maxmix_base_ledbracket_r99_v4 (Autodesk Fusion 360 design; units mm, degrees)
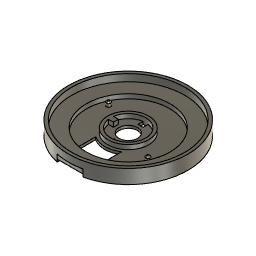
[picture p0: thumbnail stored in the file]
sketch "Sketch1" plane through (0, 0, 0) normal (0, 0, 1) x axis (1, 0, 0)
  circle C1 centre (0, 0) radius 22.95
  circle C2 centre (0, 0) radius 6.75
  circle C3 centre (0, 0) radius 21.75
  circle C4 centre (0, 0) radius 3.6
  circle C5 centre (0, 0) radius 7.9
  point P1 (0, 0)
  point P2 (0, 0)
  point P3 (0, 0)
  point P4 (0, 0)
  coincident P1 P2
  coincident P1 P3
  coincident P1 P4
  concentric C1 C4
  concentric C1 C5
  dimension "d1" diameter C1 = 45.9
  dimension "d2" diameter C3 = 43.5
  dimension "d3" diameter C4 = 7.2
  dimension "d4" diameter C2 = 13.5
  dimension "d5" diameter C5 = 15.8
extrude "Extrude1" new body sketch "Sketch1" profile of C2 C3 C4 C5 along normal blind 1
extrude "Extrude2" add sketch "Sketch1" profile of C1 C3 along normal blind 5.4
extrude "Extrude3" add sketch "Sketch1" profile of C2 C5 along normal blind 2.7
sketch "Sketch4" plane through (0, 0, 1) normal (0, 0, 1) x axis (-1, 0, 0)
  line L1 (0, 6.75) -> (0, -6.75)
  line L2 (0.95, 4.75) -> (0.95, 6.6828)
  line L3 (-0.95, 4.75) -> (0.95, 4.75)
  line L4 (-0.95, 6.6828) -> (-0.95, 4.75)
  line L5 (0.95, -4.75) -> (0.95, -6.6828)
  line L6 (-0.95, -4.75) -> (0.95, -4.75)
  line L7 (-0.95, -6.6828) -> (-0.95, -4.75)
  line L8 (-6.75, 0) -> (6.75, 0)
  line L9 (4.75, 0.95) -> (6.6828, 0.95)
  line L10 (4.75, -0.95) -> (4.75, 0.95)
  line L11 (6.6828, -0.95) -> (4.75, -0.95)
  circle C1 centre (0, 0) radius 3.6
  circle C2 centre (0, 0) radius 6.75
  circle C3 centre (0, 0) radius 6.75
  point P1 (0, 0)
  point P4 (0, -6.75)
  point P5 (0, 6.75)
  point P6 (0.95, 6.6828)
  point P9 (-0.95, 6.6828)
  point P10 (0.95, -6.6828)
  point P13 (-0.95, -6.6828)
  point P14 (-6.75, 0)
  point P15 (6.75, 0)
  point P16 (6.6828, 0.95)
  point P19 (6.6828, -0.95)
  vertical L1
  coincident P1 L1
  coincident C2 P4
  coincident C2 P5
  coincident C3 P6
  vertical L2
  perpendicular L2 L3
  coincident C3 P9
  perpendicular L3 L4
  coincident C3 P10
  vertical L5
  perpendicular L5 L6
  coincident C2 P13
  perpendicular L6 L7
  symmetric L1 L5 L7
  collinear L4 L7
  horizontal L8
  coincident P1 L8
  coincident C2 P14
  coincident C2 P15
  symmetric L3 L6 L8
  coincident C3 P16
  coincident C3 P19
  perpendicular L10 L11
  symmetric L8 L9 L11
  equal L5 L11
  equal L6 L10
  dimension "d19" distance L2 L4 = 1.9
  dimension "d20" distance P1 L3 = 4.75
  dimension "d33" distance P1 L10 = 4.75
extrude "Extrude6" add sketch "Sketch4" profile of C2 C3 L9 L10 L11 to an object
extrude "Extrude7" cut sketch "Sketch4" profile of C2 C3 L2 L3 L4 L5 L6 L7 no distance stored
sketch "Sketch2" plane through (0, 0, 1) normal (0, 0, 1) x axis (-1, 0, 0)
  circle C1 centre (0, 0) radius 7.9
  circle C2 centre (0, 0) radius 21.75
  circle C3 centre (0, 0) radius 16.1
  circle C4 centre (0, 0) radius 21.75
  point P1 (0, 0)
  point P3 (0, 0)
  coincident P1 P3
  dimension "d12" diameter C3 = 32.2
extrude "Extrude4" add sketch "Sketch2" profile of C2 C3 C4 along normal blind 1.7
sketch "Sketch3" plane through (0, 0, 0) normal (0, 0, -1) x axis (1, 0, 0)
  line L1 (22.95, 0) -> (-22.95, 0)
  line L2 (0, 22.95) -> (0, -22.95)
  line L3 (5, 7.5434) -> (5, 22.3987)
  line L4 (-5, 7.5434) -> (-5, 22.3987)
  line L5 (0.95, -4.75) -> (-0.95, -4.75)
  line L6 (0.95, -6.6828) -> (0.95, -4.75)
  line L7 (-0.95, -4.75) -> (-0.95, -6.6828)
  line L8 (-0.95, 6.6828) -> (-0.95, 4.75)
  line L9 (0.95, 4.75) -> (0.95, 6.6828)
  line L10 (-0.95, 4.75) -> (0.95, 4.75)
  circle C1 centre (0, 0) radius 3.6
  circle C2 centre (0, 0) radius 22.95
  circle C3 centre (0, 0) radius 22.95
  circle C4 centre (0, 0) radius 9.05
  arc A1 centre (0, 0) radius 6.75 clockwise from (0.95, -6.6828) to (-0.95, -6.6828)
  arc A2 centre (0, 0) radius 6.75 clockwise from (-0.95, 6.6828) to (0.95, 6.6828)
  point P4 (0, 0)
  point P1 (0, 0)
  point P5 (22.95, 0)
  point P6 (0, -22.95)
  point P7 (-22.95, 0)
  point P8 (0, 22.95)
  point P9 (5, 7.5434)
  point P10 (-5, 7.5434)
  point P11 (-5, 22.3987)
  point P12 (5, 22.3987)
  concentric C1 C4
  horizontal L1
  coincident P4 L1
  vertical L2
  coincident P1 L2
  coincident C2 P5
  coincident C2 P6
  coincident C2 P7
  coincident C2 P8
  coincident C4 P9
  coincident C4 P10
  coincident C2 P11
  coincident C2 P12
  dimension "d16" diameter C4 = 18.1
  dimension "d17" distance L3 L4 = 10
extrude "Extrude5" cut sketch "Sketch3" profile of C2 C3 C4 L3 L4 to an object
sketch "Sketch5" plane through (0, 0, 1) normal (0, 0, 1) x axis (-1, 0, 0)
  line L1 (-5, 15.3039) -> (-5, 7.5434)
  line L2 (5, 7.5434) -> (5, 15.3039)
  line L3 (-22.5, 0) -> (-1.75, 0)
  line L4 (-12.9343, 5.3576) -> (12.9343, -5.3576)
  arc A1 centre (0, 0) radius 16.1 clockwise from (5, 15.3039) to (-5, 15.3039)
  arc A2 centre (0, 0) radius 9.05 clockwise from (-5, 7.5434) to (5, 7.5434)
  circle C1 centre (0, 0) radius 7.9
  circle C2 centre (12.9343, -5.3576) radius 0.85
  circle C3 centre (-12.9343, 5.3576) radius 0.85
  point P1 (0, 0)
  point P9 (12.9343, -5.3576)
  point P11 (12.9343, -5.3576)
  point P10 (-12.9343, 5.3576)
  point P12 (-12.9343, 5.3576)
  midpoint P1 L4
  coincident P9 P11
  coincident P10 P12
  equal C2 C3
  dimension "d25" distance P9 P10 = 28
  dimension "d26" diameter C2 = 1.7
  dimension "d31" angle L3 L4 = 22.5
extrude "Extrude8" add sketch "Sketch5" profile of C2 C3 to an object
chamfer "Chamfer1" distance 0.5
sketch "Sketch6" plane through (0, 0, 2.7) normal (0, 0, 1) x axis (-1, 0, 0)
  line L1 (5, 15.3039) -> (5, 22.3987)
  line L2 (-5, 15.3039) -> (-5, 22.3987)
  arc A1 centre (0, 0) radius 16.1 clockwise from (5, 15.3039) to (-5, 15.3039)
  arc A2 centre (0, 0) radius 16.1 clockwise from (-5, 15.3039) to (5, 15.3039)
  arc A3 centre (0, 0) radius 22.95 clockwise from (-5, 22.3987) to (5, 22.3987)
  point P2 (-5, 15.3039)
  point P9 (-5, 15.3039)
  point P4 (5, 15.3039)
  point P8 (5, 15.3039)
  point P10 (5, 22.3987)
  point P13 (5, 22.3987)
  point P11 (-5, 22.3987)
  point P14 (-5, 22.3987)
  point P6 (-5, 15.3039)
  point P15 (-5, 15.3039)
  point P1 (0, 0)
  point P7 (0, 0)
  coincident P2 P9
  coincident P4 P8
  coincident P10 P13
  coincident P11 P14
  coincident P6 P15
  coincident P1 P7
sketch "Sketch7" plane through (0, 0, 1) normal (0, 0, 1) x axis (-1, 0, 0)
  line L1 (-5, 15.3039) -> (-5, 7.5434)
  line L2 (5, 7.5434) -> (5, 15.3039)
  line L3 (-5, 16.1) -> (5, 16.1)
  line L4 (-5, 22.3987) -> (5, 22.3987)
  line L5 (5, 16.1) -> (5, 22.3987)
  line L6 (-5, 22.3987) -> (-5, 16.1)
  circle C1 centre (-12.9343, 5.3576) radius 0.85
  circle C2 centre (12.9343, -5.3576) radius 0.85
  arc A1 centre (0, 0) radius 16.1 clockwise from (5, 15.3039) to (-5, 15.3039)
  arc A2 centre (0, 0) radius 9.05 clockwise from (-5, 7.5434) to (5, 7.5434)
  circle C3 centre (0, 0) radius 7.9
  arc A3 centre (0, 0) radius 16.1 clockwise from (-5, 15.3039) to (5, 15.3039)
  point P10 (-5, 15.3039)
  point P13 (-5, 15.3039)
  point P9 (5, 15.3039)
  point P12 (5, 15.3039)
  point P16 (5, 22.3987)
  point P18 (5, 22.3987)
  point P17 (-5, 22.3987)
  point P19 (-5, 22.3987)
  point P1 (0, 0)
  point P11 (0, 0)
  coincident P10 P13
  coincident P9 P12
  tangent A3 L3
  coincident P16 P18
  coincident P17 P19
  perpendicular L3 L5
  perpendicular L4 L6
  coincident P1 P11
  parallel L5 L6
loft "Loft1" sketch "Sketch7" + "Sketch6"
